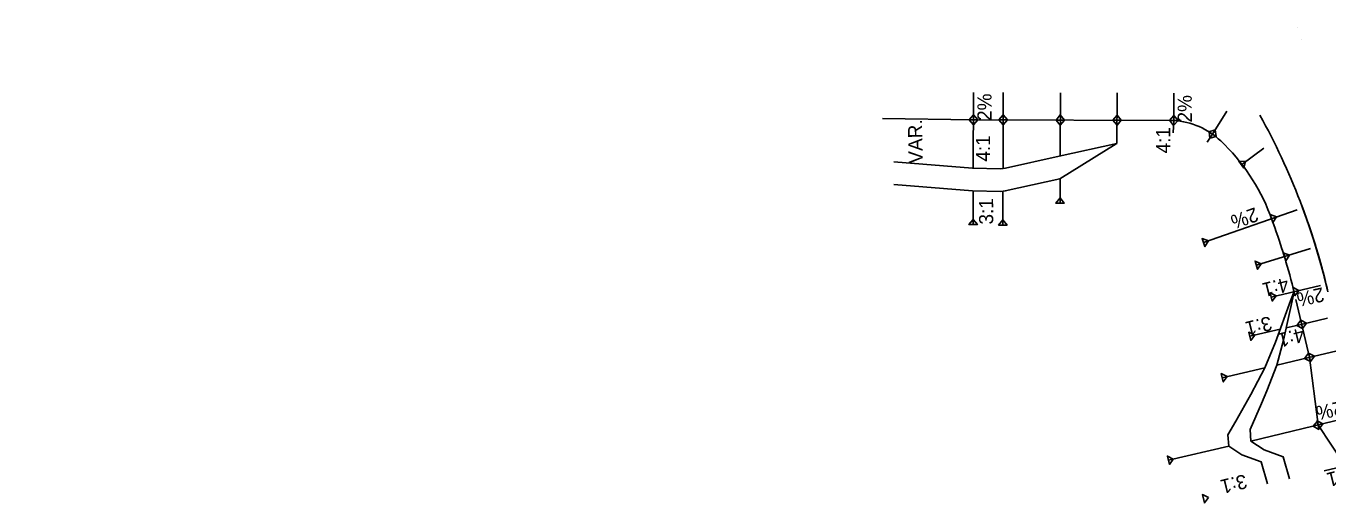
# Model space of a CAD drawing. Extents: x 2957411 to 5201395, y -5659629 to 3720102.
# Drawn here: x 5196292 to 5196866, y 3709150 to 3709360 of the extents above; entities that cross this region are included whole.
import ezdxf

# ---------------------------------------------------------------- set-up
doc = ezdxf.new("R2010")
doc.units = 0
for name, color, linetype in [('Default', 7, 'Continuous'), ('dsnProfileGradePropLine', 7, 'Continuous'), ('EdgeUnpaved', 7, 'Continuous'), ('TES', 7, 'Continuous'), ('TL_Backslope', 7, 'Continuous')]:
    doc.layers.add(name, color=color, linetype=linetype)

msp = doc.modelspace()

# ---------------------------------------------------------------- linework, layer by layer
at = {"layer": 'Default'}
msp.add_arc((5196573.59, 3709175.1), 300, 13.09646, 29.06699, dxfattribs=at)
at = {"layer": 'dsnProfileGradePropLine'}
for centre, start, end in [((5196592.28, 3709519.5), 6.5287, 6.5287), ((5196573.59, 3709175.1), 19.1288, 20.69489), ((5196573.59, 3709175.1), 13.09646, 20.69489), ((5196573.59, 3709175.1), 13.81749, 20.69489), ((5196573.59, 3709175.1), 15.72734, 20.04933), ((5196573.59, 3709175.1), 13.81749, 19.87217), ((5196573.59, 3709175.1), 13.81749, 19.1288), ((5196573.59, 3709175.1), 13.09646, 15.72734), ((5196573.59, 3709175.1), 13.09646, 13.81749), ((5196573.59, 3709175.1), 13.09646, 13.81749), ((5196573.59, 3709175.1), 13.09646, 13.81749), ((5196573.59, 3709175.1), 13.09646, 13.81558)]:
    msp.add_arc(centre, 300, start, end, dxfattribs=at)
at = {"layer": 'EdgeUnpaved'}
for p, q in [((5196852.51, 3709359.63), (5196852.51, 3709359.63)), ((5196854.05, 3709354.01), (5196854.05, 3709354.01))]:
    msp.add_line(p, q, dxfattribs=at)
at = {"layer": 'TES'}
for p, q in [((5196709.56, 3709297.58), (5196709.66, 3709330.84)), ((5196722.66, 3709297.42), (5196722.76, 3709330.81)), ((5196747.82, 3709302.88), (5196747.9, 3709330.73)), ((5196772.71, 3709308.35), (5196772.9, 3709330.66)), ((5196797.87, 3709318.53), (5196797.9, 3709330.55)), ((5196814.94, 3709312.52), (5196821.31, 3709322.71)), ((5196709.62, 3709318.84), (5196669.62, 3709319.46)), ((5196709.62, 3709318.84), (5196797.87, 3709318.53)), ((5196797.87, 3709318.53), (5196797.54, 3709313.15)), ((5196814.94, 3709312.52), (5196812.61, 3709309.04)), ((5196827.84, 3709299.24), (5196837.55, 3709306.33)), ((5196747.79, 3709292.88), (5196747.76, 3709282.19)), ((5196709.53, 3709287.56), (5196709.49, 3709272.73)), ((5196722.63, 3709287.42), (5196722.59, 3709272.51)), ((5196810.95, 3709264.78), (5196852.25, 3709279.29)), ((5196834.28, 3709254.86), (5196858.07, 3709262.14)), ((5196840.79, 3709240.81), (5196862.52, 3709245.98)), ((5196849.96, 3709246.71), (5196850.82, 3709243.26)), ((5196851.66, 3709239.79), (5196857.61, 3709214.25)), ((5196844.68, 3709226.66), (5196831.36, 3709223.56)), ((5196861.46, 3709184.61), (5196857.47, 3709215.44)), ((5196837.91, 3709209.67), (5196819.23, 3709205.32)), ((5196831.82, 3709177.45), (5196873.12, 3709187.42)), ((5196873.31, 3709166.59), (5196861.39, 3709184.69)), ((5196822.08, 3709175.19), (5196795.5, 3709169)), ((5196877.21, 3709167.5), (5196864.06, 3709164.44))]:
    msp.add_line(p, q, dxfattribs=at)
for points in [[(5196674.54, 3709290.32), (5196709.18, 3709287.59), (5196721.64, 3709287.32), (5196723.64, 3709287.52), (5196747.66, 3709292.85), (5196772.48, 3709308.26), (5196772.71, 3709308.4)], [(5196772.71, 3709308.4), (5196747.42, 3709302.79), (5196723.67, 3709297.52), (5196721.67, 3709297.32), (5196709.21, 3709297.59), (5196674.57, 3709300.32)], [(5196839.14, 3709158.63), (5196836.37, 3709168.33), (5196827.89, 3709171.4), (5196822.08, 3709175.19), (5196821.71, 3709180.23), (5196825.19, 3709186.18), (5196831.8, 3709197.98), (5196837.91, 3709209.67), (5196842.63, 3709221.04), (5196849.27, 3709239.24), (5196850.83, 3709243.28)], [(5196848.88, 3709160.89), (5196846.11, 3709170.59), (5196837.63, 3709173.67), (5196831.82, 3709177.45), (5196831.45, 3709182.5), (5196834.05, 3709188.24), (5196836.5, 3709193.94), (5196838.88, 3709199.63), (5196843.23, 3709210.91), (5196846.18, 3709221.86), (5196850.85, 3709243.2)], [(5196847.33, 3709227.24), (5196853.91, 3709228.77), (5196865.61, 3709231.49)], [(5196843.23, 3709210.91), (5196857.31, 3709214.18), (5196869.29, 3709216.97)]]:
    msp.add_lwpolyline(points, dxfattribs=at)
for centre, radius, start, end in [((5196795.87, 3709285.59), 33, 46.57533, 86.52419), ((5196758.06, 3709245.65), 88, 20.92808, 46.57533), ((5196573.59, 3709175.1), 285.5, 14.52555, 20.92808)]:
    msp.add_arc(centre, radius, start, end, dxfattribs=at)
at = {"layer": 'TL_Backslope'}
for points in [[(5196709.63, 3709321.09), (5196707.75, 3709318.85), (5196711.5, 3709318.84)], [(5196709.61, 3709316.59), (5196707.75, 3709318.85), (5196711.5, 3709318.84)], [(5196722.73, 3709321.06), (5196720.85, 3709318.81), (5196724.6, 3709318.8)], [(5196722.72, 3709316.56), (5196720.85, 3709318.81), (5196724.6, 3709318.8)], [(5196747.87, 3709320.98), (5196745.99, 3709318.74), (5196749.74, 3709318.73)], [(5196747.86, 3709316.48), (5196745.99, 3709318.74), (5196749.74, 3709318.73)], [(5196772.87, 3709320.91), (5196770.99, 3709318.67), (5196774.74, 3709318.66)], [(5196772.86, 3709316.41), (5196770.99, 3709318.67), (5196774.74, 3709318.66)], [(5196797.87, 3709320.78), (5196795.99, 3709318.54), (5196799.74, 3709318.53)], [(5196797.8, 3709316.35), (5196795.99, 3709318.65), (5196799.74, 3709318.54)], [(5196816.13, 3709314.43), (5196813.35, 3709313.52), (5196816.53, 3709311.53)], [(5196813.72, 3709310.7), (5196813.41, 3709313.61), (5196816.53, 3709311.53)], [(5196829.5, 3709300.45), (5196826.58, 3709300.64), (5196828.79, 3709297.61)], [(5196747.76, 3709284.44), (5196745.88, 3709282.19), (5196749.63, 3709282.18)], [(5196843.08, 3709276.09), (5196840.34, 3709277.13), (5196841.57, 3709273.58)], [(5196709.49, 3709274.98), (5196707.61, 3709272.74), (5196711.36, 3709272.73)], [(5196722.59, 3709274.76), (5196720.71, 3709272.51), (5196724.46, 3709272.5)], [(5196813.11, 3709265.56), (5196810.37, 3709266.6), (5196811.6, 3709263.05)], [(5196848.77, 3709259.23), (5196846.07, 3709260.36), (5196847.16, 3709256.78)], [(5196836.41, 3709255.52), (5196833.71, 3709256.65), (5196834.81, 3709253.07)], [(5196842.99, 3709241.39), (5196840.38, 3709242.7), (5196841.23, 3709239.05)], [(5196853.01, 3709243.77), (5196850.4, 3709245.09), (5196851.24, 3709241.43)], [(5196833.53, 3709224.07), (5196830.92, 3709225.38), (5196831.77, 3709221.73)], [(5196852.03, 3709228.35), (5196853.82, 3709230.67), (5196854.64, 3709227.01)], [(5196856.4, 3709229.35), (5196853.79, 3709230.66), (5196854.64, 3709227.01)], [(5196855.42, 3709213.76), (5196857.21, 3709216.08), (5196858.03, 3709212.42)], [(5196859.8, 3709214.76), (5196857.18, 3709216.08), (5196858.03, 3709212.42)], [(5196821.41, 3709205.83), (5196818.79, 3709207.15), (5196819.64, 3709203.5)], [(5196859.21, 3709184.09), (5196861.14, 3709186.29), (5196861.72, 3709182.58)], [(5196863.6, 3709185.12), (5196860.99, 3709186.44), (5196861.84, 3709182.79)], [(5196797.67, 3709169.51), (5196795.06, 3709170.83), (5196795.91, 3709167.17)], [(5196813.13, 3709152.58), (5196810.51, 3709153.9), (5196811.36, 3709150.24)]]:
    msp.add_lwpolyline(points, close=True, dxfattribs=at)

# ---------------------------------------------------------------- texts
at = {"layer": 'Default'}
for s, rotation, p in [('2%', 90.15309, (5196717.62, 3709318.36)), ('2%', 90.15309, (5196805.83, 3709317.67)), ('VAR.', 90.99179, (5196687.3, 3709299.61)), ('4:1', 90.15309, (5196716.96, 3709300.44)), ('4:1', 90.15309, (5196796.33, 3709304.04)), ('3:1', 90.15309, (5196718.33, 3709272.77)), ('2%', 199.41906, (5196833.74, 3709280.45)), ('4:1', 193.78879, (5196847.64, 3709249.56)), ('2%', 192.69041, (5196863.34, 3709245.18)), ('3:1', 193.78879, (5196840.2, 3709232.52)), ('4:1', 193.78879, (5196854.51, 3709227.4)), ('2%', 192.69041, (5196871.75, 3709195.24)), ('3:1', 193.78879, (5196829.22, 3709162.96)), ('6:1', 194.07116, (5196876.02, 3709166.07))]:
    msp.add_text(s, height=6.24, rotation=rotation, dxfattribs=at).set_placement(p)

doc.saveas('drawing.dxf')
